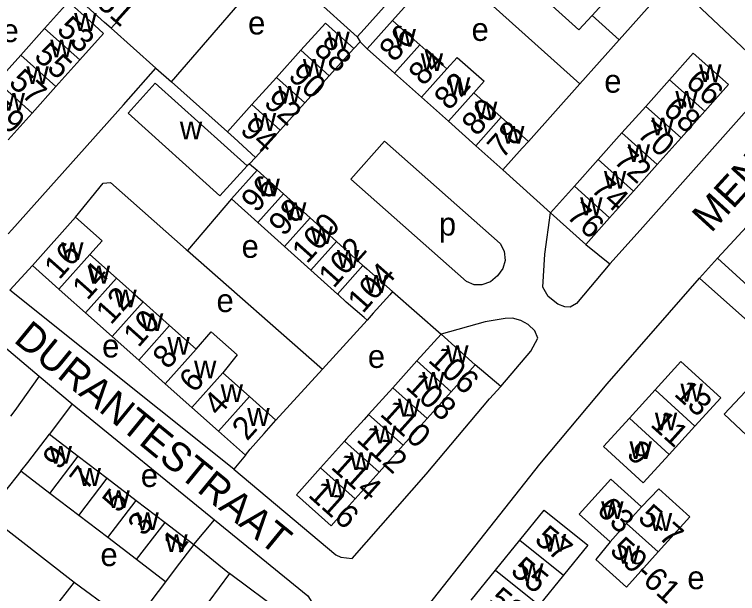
# Model space of a CAD drawing. Extents: x 159045 to 160918, y 380454 to 382516.
# Drawn here: x 159439.6 to 159564.5, y 381948.4 to 382048.4 of the extents above; entities that cross this region are included whole.
import ezdxf

# ---------------------------------------------------------------- set-up
doc = ezdxf.new("R2010")
doc.units = 0
for name, color, linetype in [('BLT_Basislijn', 7, 'Continuous'), ('BLT_Bebouwing', 7, 'Continuous'), ('BLT_Centroide', 7, 'Continuous'), ('BLT_Huisnummer', 7, 'Continuous'), ('BLT_Huisnummer_ tussenligend', 7, 'Continuous'), ('BLT_Huisnummer_reeks', 7, 'Continuous'), ('BLT_Onderverdeling_panden', 7, 'Continuous'), ('BLT_Straatnaam', 7, 'Continuous')]:
    doc.layers.add(name, color=color, linetype=linetype)

msp = doc.modelspace()

# ---------------------------------------------------------------- linework, layer by layer
at = {"layer": 'BLT_Basislijn'}
for p, q in [((159466.74, 382036.77), (159484.51, 382057.46)), ((159504.93, 382047.4), (159513.87, 382057.42)), ((159513.87, 382057.42), (159537.25, 382036.45)), ((159456.36, 382046.04), (159464.04, 382039.18)), ((159498.21, 382042.54), (159499.33, 382043.68)), ((159498.82, 382044.57), (159499.33, 382043.68)), ((159499.33, 382043.68), (159500.54, 382042.48)), ((159537.25, 382036.45), (159544.04, 382044.06)), ((159593.23, 382041.2), (159561, 382006.34)), ((159464.04, 382039.18), (159466.74, 382036.77)), ((159466.74, 382036.77), (159476.4, 382028.15)), ((159528.36, 382026.49), (159537.25, 382036.45)), ((159481.28, 382023.75), (159480.23, 382022.62)), ((159480.23, 382022.62), (159479.79, 382022.3)), ((159480.23, 382022.62), (159481.55, 382021.53)), ((159523.98, 382021.58), (159532.2, 382014.15)), ((159477.09, 382016.58), (159469.5, 382007.64)), ((159547.64, 382011.18), (159542.42, 382005.33)), ((159538.29, 382008.72), (159542.42, 382005.33)), ((159469.5, 382007.64), (159492.8, 381987.14)), ((159557.92, 382002.85), (159561, 382006.34)), ((159594.06, 381976.07), (159561, 382006.34)), ((159438.83, 382000.81), (159442.73, 382005.06)), ((159477.49, 381969.9), (159438.83, 382000.81)), ((159504.91, 382000.55), (159513.29, 381993.18)), ((159500.52, 381995.61), (159492.8, 381987.14)), ((159523.58, 381984.19), (159519.2, 381987.88)), ((159492.8, 381987.14), (159484.79, 381978.34)), ((159443.91, 381985.92), (159449.63, 381981.17)), ((159523.58, 381984.19), (159521.67, 381982.04)), ((159449.63, 381981.17), (159445.66, 381975.93)), ((159449.63, 381981.17), (159474.15, 381961.14)), ((159479.5, 381972.32), (159477.49, 381969.9)), ((159470.62, 381956.86), (159474.15, 381961.14)), ((159470.62, 381956.86), (159476.79, 381951.88)), ((159449.92, 381950.36), (159442.39, 381940.67)), ((159449.92, 381950.36), (159460.02, 381942.98)), ((159465.72, 381950.44), (159460.02, 381942.98))]:
    msp.add_line(p, q, dxfattribs=at)
for points in [[(159547.64, 382011.18), (159569.75, 382036.02), (159569.64, 382038.11), (159569.12, 382039.17), (159553.28, 382054.14)], [(159438.58, 382010.52), (159439.2, 382011.2), (159458.45, 382032.81), (159464.04, 382039.18)], [(159523.52, 382008.85), (159503.51, 382026.56), (159497.7, 382020), (159517.68, 382002.3)], [(159450.18, 382013.41), (159454.94, 382019.26), (159456.21, 382019.42), (159469.29, 382007.82), (159469.5, 382007.64)], [(159542.42, 382005.33), (159536.66, 381998.5), (159535.59, 381997.84), (159534.64, 381997.93), (159533.46, 381998.37), (159531.78, 381999.7), (159530.85, 382001.32), (159531.22, 382007.05), (159532.2, 382014.15)], [(159523.52, 382008.85), (159524.18, 382007.52), (159524.36, 382005.95), (159523.98, 382004.52), (159523.01, 382003.26), (159521.84, 382002.26), (159520.34, 382001.74), (159518.98, 382001.72), (159517.68, 382002.3)], [(159557.92, 382002.85), (159569.85, 381992.2), (159593.34, 381970.78), (159604.26, 381960.81), (159603.62, 381953.08), (159578.72, 381929.8), (159553.77, 381902.89), (159547.43, 381902.07), (159522.11, 381926.2), (159505.97, 381939.82)], [(159505.97, 381939.82), (159530.32, 381970.73), (159541.99, 381984.63), (159557.92, 382002.85)], [(159419.74, 381994.69), (159420.98, 381996.2), (159423.95, 381998.17), (159425.15, 381998.47), (159427.71, 381998.3), (159429.98, 381997.7), (159443.91, 381985.92)], [(159523.58, 381984.19), (159528.77, 381990.26), (159530, 381992.5), (159529.47, 381993.75), (159528.31, 381994.86), (159527.08, 381995.59), (159525.61, 381995.99), (159524.33, 381995.92), (159520.88, 381995.31), (159513.29, 381993.18)], [(159443.91, 381985.92), (159439.69, 381980.04), (159438.94, 381979.06)], [(159477.49, 381969.9), (159495.12, 381955.09), (159495.97, 381954.66), (159497.97, 381954.45), (159510.74, 381969.04), (159521.67, 381982.04)], [(159440.76, 381969.52), (159435.06, 381962.4), (159435.06, 381961.92), (159449.92, 381950.36)], [(159474.15, 381961.14), (159490.26, 381947.98), (159491.29, 381946.43), (159491.17, 381944.89), (159466.84, 381912.21)]]:
    msp.add_lwpolyline(points, dxfattribs=at)
at = {"layer": 'BLT_Bebouwing'}
for p, q in [((159484.51, 382057.46), (159498.82, 382044.57)), ((159460.55, 382050.7), (159456.36, 382046.04)), ((159504.93, 382047.4), (159500.54, 382042.48)), ((159539.38, 382048.23), (159544.04, 382044.06)), ((159444.85, 382046.01), (159440.73, 382041.42)), ((159489.1, 382042.25), (159484.86, 382037.55)), ((159498.21, 382042.54), (159493.98, 382037.85)), ((159500.54, 382042.48), (159505.23, 382038.3)), ((159509.61, 382043.21), (159514.3, 382039.03)), ((159440.73, 382041.42), (159436.61, 382036.83)), ((159446.79, 382035.98), (159450.91, 382040.58)), ((159484.86, 382037.55), (159480.63, 382032.85)), ((159493.98, 382037.85), (159489.75, 382033.15)), ((159505.23, 382038.3), (159509.92, 382034.12)), ((159552.74, 382037.16), (159548.63, 382032.56)), ((159442.67, 382031.39), (159446.79, 382035.98)), ((159518.93, 382034.9), (159523.67, 382030.67)), ((159509.92, 382034.12), (159514.55, 382029.99)), ((159480.63, 382032.85), (159476.4, 382028.15)), ((159489.75, 382033.15), (159485.52, 382028.45)), ((159548.63, 382032.56), (159544.52, 382027.96)), ((159438.55, 382026.8), (159442.67, 382031.39)), ((159554.72, 382027.12), (159558.83, 382031.72)), ((159514.55, 382029.99), (159519.29, 382025.76)), ((159523.67, 382030.67), (159528.36, 382026.49)), ((159485.52, 382028.45), (159481.28, 382023.75)), ((159544.52, 382027.96), (159540.41, 382023.36)), ((159550.61, 382022.52), (159554.72, 382027.12)), ((159519.29, 382025.76), (159523.98, 382021.58)), ((159540.41, 382023.36), (159536.31, 382018.76)), ((159546.5, 382017.92), (159550.61, 382022.52)), ((159477.09, 382016.58), (159481.55, 382021.53)), ((159481.55, 382021.53), (159486.1, 382017.42)), ((159536.31, 382018.76), (159532.2, 382014.15)), ((159486.1, 382017.42), (159490.67, 382013.3)), ((159542.39, 382013.32), (159546.5, 382017.92)), ((159481.67, 382012.47), (159477.09, 382016.58)), ((159532.2, 382014.15), (159538.29, 382008.72)), ((159442.73, 382005.06), (159450.18, 382013.41)), ((159486.24, 382008.36), (159481.67, 382012.47)), ((159490.67, 382013.3), (159495.24, 382009.19)), ((159538.29, 382008.72), (159542.39, 382013.32)), ((159495.24, 382009.19), (159499.81, 382005.07)), ((159490.82, 382004.24), (159486.24, 382008.36)), ((159452.67, 382006.98), (159457.26, 382002.89)), ((159447.31, 382000.97), (159442.73, 382005.06)), ((159495.39, 382000.13), (159490.82, 382004.24)), ((159461.85, 381998.8), (159466.43, 381994.71)), ((159451.9, 381996.88), (159456.49, 381992.79)), ((159466.43, 381994.71), (159471.02, 381990.62)), ((159456.49, 381992.79), (159461.09, 381988.7)), ((159509.12, 381988.57), (159513.29, 381993.18)), ((159513.29, 381993.18), (159519.2, 381987.88)), ((159461.09, 381988.7), (159465.68, 381984.61)), ((159504.95, 381983.96), (159509.12, 381988.57)), ((159519.2, 381987.88), (159515.05, 381983.26)), ((159475.61, 381986.53), (159480.2, 381982.43)), ((159465.68, 381984.61), (159470.27, 381980.53)), ((159500.79, 381979.35), (159504.95, 381983.96)), ((159550.26, 381983.57), (159545.8, 381978.68)), ((159480.2, 381982.43), (159484.79, 381978.34)), ((159515.05, 381983.26), (159510.9, 381978.63)), ((159470.27, 381980.53), (159474.86, 381976.44)), ((159510.9, 381978.63), (159506.75, 381974)), ((159552.67, 381972.43), (159557.12, 381977.32)), ((159474.86, 381976.44), (159479.5, 381972.32)), ((159445.66, 381975.93), (159450.65, 381972.11)), ((159496.63, 381974.72), (159492.49, 381970.09)), ((159506.75, 381974), (159502.6, 381969.37)), ((159450.65, 381972.11), (159455.64, 381968.3)), ((159445.75, 381965.7), (159440.76, 381969.52)), ((159455.64, 381968.3), (159460.64, 381964.49)), ((159450.74, 381961.89), (159445.75, 381965.7)), ((159460.64, 381964.49), (159465.63, 381960.67)), ((159455.74, 381958.07), (159450.74, 381961.89)), ((159465.63, 381960.67), (159470.62, 381956.86)), ((159460.73, 381954.26), (159455.74, 381958.07)), ((159522.7, 381952.43), (159526.89, 381957.62)), ((159465.72, 381950.44), (159460.73, 381954.26)), ((159518.51, 381947.23), (159522.7, 381952.43)), ((159534.41, 381951.56), (159530.22, 381946.36))]:
    msp.add_line(p, q, dxfattribs=at)
for points in [[(159498.82, 382044.57), (159500, 382045.88), (159503.44, 382049.77), (159500, 382052.84), (159487.58, 382064.02), (159482.94, 382058.87)], [(159534.72, 382052.4), (159532.46, 382049.9), (159537.05, 382045.79), (159539.38, 382048.23)], [(159450.91, 382040.58), (159455.03, 382045.16), (159452.7, 382047.25), (159448.97, 382050.6), (159444.85, 382046.01)], [(159456.36, 382046.04), (159455.2, 382047.07), (159451.48, 382050.41)], [(159544.04, 382044.06), (159546, 382046.25), (159549.34, 382049.98)], [(159509.61, 382043.21), (159508.66, 382044.07), (159504.93, 382047.4)], [(159498.21, 382042.54), (159494.5, 382045.89), (159493.33, 382046.94), (159489.1, 382042.25)], [(159514.3, 382039.03), (159516.09, 382041.01), (159520.71, 382036.89), (159518.93, 382034.9)], [(159558.83, 382031.72), (159562.93, 382036.32), (159556.84, 382041.76), (159552.74, 382037.16)], [(159479.79, 382022.3), (159463.95, 382036.57), (159459.27, 382031.38), (159475.11, 382017.11), (159479.79, 382022.3)], [(159476.4, 382028.15), (159477.57, 382027.1), (159481.28, 382023.75)], [(159523.98, 382021.58), (159527.31, 382025.31), (159528.36, 382026.49)], [(159450.18, 382013.41), (159454.76, 382009.32), (159452.67, 382006.98)], [(159499.81, 382005.07), (159500, 382004.9), (159500.45, 382004.5), (159504.91, 382000.55)], [(159457.26, 382002.89), (159460.5, 382000), (159461.85, 381998.8)], [(159451.9, 381996.88), (159448.39, 382000.01), (159447.31, 382000.97)], [(159500.52, 381995.61), (159500, 381996.06), (159496.93, 381998.75), (159495.57, 381999.98), (159495.39, 382000.13)], [(159504.91, 382000.55), (159504.42, 382000), (159501.59, 381996.81), (159500.52, 381995.61)], [(159471.02, 381990.62), (159473.62, 381993.62), (159478.1, 381989.63), (159475.61, 381986.53)], [(159557.12, 381977.32), (159561.57, 381982.21), (159554.71, 381988.46), (159550.26, 381983.57)], [(159573.46, 381981.67), (159568.63, 381986.22), (159562.17, 381979.37), (159567, 381974.82)], [(159500.79, 381979.35), (159500, 381978.48), (159496.93, 381975.05), (159496.63, 381974.72)], [(159545.8, 381978.68), (159541.35, 381973.79), (159548.21, 381967.54), (159552.67, 381972.43)], [(159479.5, 381972.32), (159480.32, 381973.33), (159482.76, 381976.07), (159484.79, 381978.34)], [(159440.76, 381969.52), (159441.92, 381971.04), (159445.66, 381975.93)], [(159492.49, 381970.09), (159488.34, 381965.46), (159494.3, 381960.11), (159496.93, 381963.05), (159498.45, 381964.74)], [(159498.45, 381964.74), (159500, 381966.48), (159502.6, 381969.37)], [(159547.92, 381963.38), (159542.58, 381968.17), (159537.12, 381962.09), (159542.46, 381957.3)], [(159550.78, 381955.59), (159556.24, 381961.67), (159550.91, 381966.46), (159547.92, 381963.38)], [(159526.89, 381957.62), (159531.09, 381962.82), (159538.6, 381956.75), (159534.41, 381951.56)], [(159542.46, 381957.3), (159539.99, 381954.3), (159545.32, 381949.51), (159550.78, 381955.59)], [(159470.62, 381956.86), (159467.58, 381952.88), (159465.72, 381950.44)], [(159476.79, 381951.88), (159473.17, 381947.05), (159475.63, 381945.21), (159475.48, 381945.02)], [(159482.26, 381939.92), (159486.03, 381944.93), (159476.79, 381951.88)]]:
    msp.add_lwpolyline(points, dxfattribs=at)
at = {"layer": 'BLT_Onderverdeling_panden'}
for p, q in [((159539.38, 382048.23), (159544.68, 382054.15)), ((159450.91, 382040.58), (159444.85, 382046.01)), ((159493.98, 382037.85), (159489.1, 382042.25)), ((159505.23, 382038.3), (159509.61, 382043.21)), ((159446.79, 382035.98), (159440.73, 382041.42)), ((159509.92, 382034.12), (159514.3, 382039.03)), ((159489.75, 382033.15), (159484.86, 382037.55)), ((159558.83, 382031.72), (159552.74, 382037.16)), ((159442.67, 382031.39), (159436.61, 382036.83)), ((159514.55, 382029.99), (159518.93, 382034.9)), ((159485.52, 382028.45), (159480.63, 382032.85)), ((159554.72, 382027.12), (159548.63, 382032.56)), ((159519.29, 382025.76), (159523.67, 382030.67)), ((159550.61, 382022.52), (159544.52, 382027.96)), ((159546.5, 382017.92), (159540.41, 382023.36)), ((159542.39, 382013.32), (159536.31, 382018.76)), ((159481.67, 382012.47), (159486.1, 382017.42)), ((159486.24, 382008.36), (159490.67, 382013.3)), ((159490.82, 382004.24), (159495.24, 382009.19)), ((159447.31, 382000.97), (159452.67, 382006.98)), ((159495.39, 382000.13), (159499.81, 382005.07)), ((159451.9, 381996.88), (159457.26, 382002.89)), ((159456.49, 381992.79), (159461.85, 381998.8)), ((159461.09, 381988.7), (159466.43, 381994.71)), ((159465.68, 381984.61), (159471.02, 381990.62)), ((159515.05, 381983.26), (159509.12, 381988.57)), ((159470.27, 381980.53), (159475.61, 381986.53)), ((159510.9, 381978.63), (159504.95, 381983.96)), ((159550.26, 381983.57), (159557.12, 381977.32)), ((159474.86, 381976.44), (159480.2, 381982.43)), ((159506.75, 381974), (159500.79, 381979.35)), ((159545.8, 381978.68), (159552.67, 381972.43)), ((159502.6, 381969.37), (159496.63, 381974.72)), ((159445.75, 381965.7), (159450.65, 381972.11)), ((159498.45, 381964.74), (159492.49, 381970.09)), ((159450.74, 381961.89), (159455.64, 381968.3)), ((159455.74, 381958.07), (159460.64, 381964.49)), ((159547.92, 381963.38), (159545.32, 381960.49)), ((159460.73, 381954.26), (159465.63, 381960.67)), ((159545.32, 381960.49), (159542.46, 381957.3)), ((159545.32, 381960.49), (159550.78, 381955.59)), ((159526.89, 381957.62), (159534.41, 381951.56)), ((159522.7, 381952.43), (159530.22, 381946.36))]:
    msp.add_line(p, q, dxfattribs=at)

# ---------------------------------------------------------------- texts
at = {"layer": 'BLT_Centroide'}
for s, p in [('w', (159449.95, 382045.59)), ('e', (159479.97, 382044.98)), ('e', (159437.41, 382043.66)), ('w', (159505.08, 382042.84)), ('e', (159518.55, 382043.86)), ('w', (159493.66, 382042.41)), ('w', (159445.82, 382041)), ('w', (159509.77, 382038.66)), ('w', (159489.42, 382037.69)), ('w', (159557.83, 382036.75)), ('w', (159441.7, 382036.41)), ('w', (159514.45, 382034.48)), ('e', (159541.47, 382034.92)), ('w', (159485.19, 382033)), ('w', (159437.59, 382031.81)), ('w', (159553.73, 382032.16)), ('w', (159519.14, 382030.31)), ('w', (159480.95, 382028.31)), ('w', (159468.19, 382026.84)), ('w', (159549.62, 382027.53)), ('w', (159523.83, 382026.12)), ('w', (159545.51, 382022.94)), ('w', (159541.4, 382018.34)), ('w', (159481.59, 382017)), ('w', (159486.17, 382012.89)), ('w', (159537.3, 382013.75)), ('p', (159512.91, 382010.24)), ('w', (159490.75, 382008.78)), ('w', (159447.7, 382006.02)), ('e', (159478.85, 382006.39)), ('w', (159495.31, 382004.66)), ('w', (159452.28, 382001.94)), ('w', (159500.15, 382000.34)), ('w', (159456.88, 381997.84)), ('e', (159474.52, 381997.02)), ('w', (159461.47, 381993.75)), ('e', (159454.77, 381989.18)), ('w', (159466.05, 381989.66)), ('w', (159514.17, 381988.22)), ('e', (159500.65, 381987.37)), ('w', (159470.64, 381985.56)), ('w', (159510.02, 381983.59)), ('w', (159475.23, 381981.47)), ('w', (159554.62, 381981.57)), ('w', (159505.84, 381978.97)), ('w', (159479.83, 381977.36)), ('w', (159550.2, 381976.58)), ('w', (159501.69, 381974.34)), ('w', (159445.7, 381970.83)), ('w', (159545.83, 381971.62)), ('w', (159497.55, 381969.72)), ('w', (159450.7, 381967)), ('e', (159461.45, 381966.8)), ('w', (159493.39, 381965.09)), ('w', (159455.69, 381963.17)), ('w', (159540.93, 381961.25)), ('w', (159460.69, 381959.36)), ('w', (159549.32, 381959.21)), ('w', (159465.67, 381955.55)), ('w', (159531.03, 381955.61)), ('e', (159454.48, 381953.14)), ('w', (159543.77, 381953.58)), ('w', (159527.11, 381950.53)), ('e', (159555.81, 381949.15))]:
    msp.add_text(s, height=4, dxfattribs=at).set_placement(p)
at = {"layer": 'BLT_Huisnummer'}
for s, rotation, p in [('53', 318.0923, (159446.74, 382045.54)), ('86', 48.2696, (159505.23, 382040.04)), ('88', 317.9901, (159491.13, 382042.13)), ('57', 318.0923, (159438.46, 382036.43)), ('66', 318.2423, (159555.3, 382036.42)), ('82', 48.2638, (159514.7, 382031.7)), ('94', 317.9753, (159478.4, 382028.22)), ('78', 48.2589, (159523.89, 382023.35)), ('70', 318.2476, (159546.93, 382027.55)), ('96', 48.1334, (159481.38, 382014.02)), ('76', 318.2382, (159534.75, 382013.44)), ('100', 48.1308, (159490.14, 382005.23)), ('16', 48.3127, (159447.38, 382002.47)), ('104', 48.362, (159499.77, 381996.64)), ('10', 48.3096, (159461.04, 381990.76)), ('106', 318.1338, (159510.89, 381988.54)), ('6', 48.3131, (159470.68, 381982.89)), ('13', 318.149, (159553.35, 381982.71)), ('110', 318.1282, (159502.57, 381979.24)), ('2', 48.3109, (159479.81, 381974.63)), ('11', 318.149, (159549.26, 381977.42)), ('9', 52.6132, (159447.36, 381969.6)), ('9', 318.149, (159545.12, 381972.26)), ('116', 318.149, (159490.17, 381965.25)), ('5', 52.6132, (159457.65, 381962.15)), ('63', 317.149, (159539.95, 381962.57)), ('57', 320.149, (159529.23, 381957.45)), ('1', 52.6075, (159468.08, 381955.11)), ('55', 320.149, (159525.1, 381952.02)), ('53', 320.149, (159521.14, 381946.77))]:
    msp.add_text(s, height=4, rotation=rotation, dxfattribs=at).set_placement(p)
at = {"layer": 'BLT_Huisnummer_ tussenligend'}
for s, rotation, p in [('51', 318.1048, (159453.64, 382050.1)), ('55', 318.0923, (159442.84, 382040.96)), ('84', 48.2638, (159510.28, 382035.93)), ('90', 317.9901, (159486.71, 382037.55)), ('92', 317.9901, (159482.49, 382032.96)), ('59', 318.0923, (159434.74, 382031.5)), ('80', 48.2589, (159519.47, 382027.24)), ('68', 318.2423, (159551.4, 382031.66)), ('72', 318.2476, (159542.87, 382022.96)), ('74', 318.2476, (159538.96, 382018.05)), ('98', 48.1334, (159486.13, 382009.95)), ('102', 48.1308, (159494.73, 382000.99)), ('14', 48.3096, (159452.22, 381998.91)), ('12', 48.3096, (159456.3, 381994.68)), ('8', 48.3131, (159466.11, 381986.97)), ('108', 318.1338, (159506.99, 381983.95)), ('4', 48.3109, (159474.88, 381978.86)), ('112', 318.1282, (159498.51, 381974.82)), ('114', 318.1282, (159494.09, 381970.08)), ('7', 52.6132, (159452.04, 381966.04)), ('3', 52.6075, (159462.04, 381958.14))]:
    msp.add_text(s, height=4, rotation=rotation, dxfattribs=at).set_placement(p)
at = {"layer": 'BLT_Huisnummer_reeks'}
for s, rotation, p in [('5-7', 318.9133, (159547.06, 381961.18)), ('59-61', 317.9183, (159542.22, 381955.58))]:
    msp.add_text(s, height=4, rotation=rotation, dxfattribs=at).set_placement(p)
at = {"layer": 'BLT_Straatnaam'}
for s, height, rotation, p in [('MENDELSSOHNLAAN', 5, 47.606, (159559.9, 382010.56)), ('DURANTESTRAAT', 4.9999, 320.7712, (159439.32, 381991.97))]:
    msp.add_text(s, height=height, rotation=rotation, dxfattribs=at).set_placement(p)

doc.saveas('drawing.dxf')
